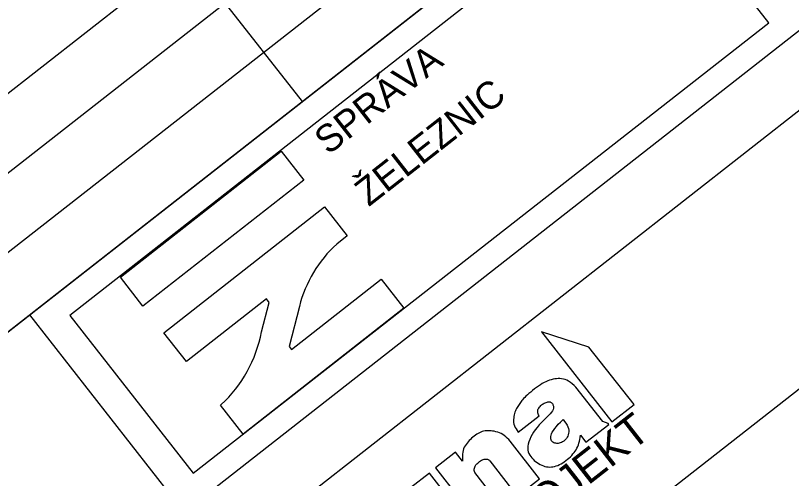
# Model space of a CAD drawing. Extents: x -651125 to -650955, y -1098339 to -1098183.
# Drawn here: x -650997.42 to -650981.93, y -1098225.14 to -1098215.9 of the extents above; entities that cross this region are included whole.
import ezdxf

# ---------------------------------------------------------------- set-up
doc = ezdxf.new("R2010")
doc.units = 0
for name, color, linetype in [('0_rozpiska', 7, 'Continuous'), ('0_rozpiska-netisk', 7, 'Continuous'), ('Default', 7, 'Continuous'), ('Rozpiska', 7, 'Continuous'), ('Rozpiska_Logo', 7, 'Continuous'), ('Rozpiska_pole_4', 7, 'Continuous'), ('Rozpiska_pole_6', 7, 'Continuous')]:
    doc.layers.add(name, color=color, linetype=linetype)

# ---------------------------------------------------------------- blocks, each defined once
blk = doc.blocks.new('_U4')
at = {"layer": 'Rozpiska_Logo'}
blk.add_lwpolyline([(-0.0008399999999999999, 0.0008199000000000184), (0.0008399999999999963, 0.0008199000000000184), (0.0008399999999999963, 0.0005175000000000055), (-0.0008399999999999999, 0.0005175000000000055)], close=True, dxfattribs=at)
for points in [[(-2.995834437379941e-06, -6.329999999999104e-05), (-0.0008399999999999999, -6.329999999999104e-05), (-0.0008399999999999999, 0.00023910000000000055), (0.0008399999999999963, 0.00023910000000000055), (0.0008399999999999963, -6.329999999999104e-05), (0.0007294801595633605, -6.330000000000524e-05)], [(-0.00020291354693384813, -0.0002497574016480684), (-2.995834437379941e-06, -9.900986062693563e-05), (-2.995834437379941e-06, -6.329999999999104e-05)], [(0.0001714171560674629, -0.0002774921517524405), (-9.743909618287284e-05, -0.00048589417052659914), (-9.743909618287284e-05, -0.0005174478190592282), (0.0008399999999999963, -0.0005174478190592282), (0.0008399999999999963, -0.000819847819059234), (-0.0008399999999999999, -0.000819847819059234), (-0.0008399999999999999, -0.0005174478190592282), (-0.0008331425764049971, -0.0005174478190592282)]]:
    blk.add_lwpolyline(points, dxfattribs=at)
for centre, radius, start, end in [((0.0008055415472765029, -0.0010955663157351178), 0.0010350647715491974, 94.21415970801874, 127.7807996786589), ((-0.0009201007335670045, 0.0005630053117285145), 0.0010839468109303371, 274.60142059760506, 311.4253943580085)]:
    blk.add_arc(centre, radius, start, end, dxfattribs=at)
blk = doc.blocks.new('_U3')
at = {"layer": 'Rozpiska_Logo'}
blk.add_blockref('_U4', (-0.0011065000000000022, -3.555000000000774e-05), dxfattribs=at)
at = {"layer": 'Rozpiska_pole_6'}
for s, p in [('SPRÁVA', (1.6969479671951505e-05, 0.0005179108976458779)), ('ŽELEZNIC', (1.6969479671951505e-05, -2.2089102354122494e-05))]:
    blk.add_text(s, height=0.00022500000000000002, dxfattribs=at).set_placement(p)
blk = doc.blocks.new('A$C346D018F')
at = {"layer": 'Rozpiska'}
for points in [[(-0.00741159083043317, 0.007120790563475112), (-0.00741159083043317, 0.012960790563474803), (-0.009651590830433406, 0.01624079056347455), (-0.009651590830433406, 0.007120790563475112)], [(-0.036140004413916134, 0.0068858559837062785), (-0.03577818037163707, 0.006902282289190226), (-0.03541167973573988, 0.006950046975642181), (-0.035040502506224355, 0.0070291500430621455), (-0.03466464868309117, 0.0071395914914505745), (-0.03430989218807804, 0.007275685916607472), (-0.034002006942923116, 0.007431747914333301), (-0.03374099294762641, 0.007607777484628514), (-0.033526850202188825, 0.0078037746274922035), (-0.033359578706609, 0.008019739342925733), (-0.03323917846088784, 0.00825567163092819), (-0.0331656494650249, 0.008511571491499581), (-0.03313899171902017, 0.008787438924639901), (-0.03314962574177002, 0.009060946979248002), (-0.03318797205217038, 0.009309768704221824), (-0.03325403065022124, 0.009533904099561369), (-0.03334780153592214, 0.009733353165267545), (-0.03346928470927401, 0.009908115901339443), (-0.03361848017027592, 0.010058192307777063), (-0.033795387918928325, 0.01018358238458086), (-0.03400000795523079, 0.010284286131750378), (-0.03421963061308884, 0.010370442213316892), (-0.03444154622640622, 0.01045218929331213), (-0.03466575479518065, 0.010529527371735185), (-0.03489225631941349, 0.01060245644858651), (-0.035121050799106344, 0.010670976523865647), (-0.03535213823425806, 0.010735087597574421), (-0.03558551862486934, 0.010794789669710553), (-0.035821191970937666, 0.010850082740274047), (-0.03604279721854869, 0.01090517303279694), (-0.036233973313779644, 0.010964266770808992), (-0.03639472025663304, 0.011027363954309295), (-0.03652503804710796, 0.011094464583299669), (-0.03662492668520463, 0.01116556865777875), (-0.036694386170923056, 0.011240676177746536), (-0.036733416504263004, 0.01131978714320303), (-0.03674201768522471, 0.01140290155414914), (-0.03672548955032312, 0.011482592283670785), (-0.036689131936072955, 0.011551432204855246), (-0.036632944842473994, 0.011609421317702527), (-0.03655692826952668, 0.011656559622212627), (-0.036461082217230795, 0.011692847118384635), (-0.03634540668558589, 0.01171828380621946), (-0.036209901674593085, 0.01173286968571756), (-0.036054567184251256, 0.011736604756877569), (-0.03589937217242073, 0.01172578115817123), (-0.03576428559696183, 0.011696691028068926), (-0.035649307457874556, 0.011649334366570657), (-0.03555443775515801, 0.011583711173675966), (-0.03547967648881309, 0.011499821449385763), (-0.035425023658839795, 0.011397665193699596), (-0.035390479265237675, 0.011277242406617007), (-0.035376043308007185, 0.011138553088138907), (-0.033297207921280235, 0.011138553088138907), (-0.03331636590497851, 0.011380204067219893), (-0.03337848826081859, 0.01160998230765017), (-0.03348350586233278, 0.011827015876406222), (-0.03363141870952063, 0.012031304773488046), (-0.03382222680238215, 0.012222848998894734), (-0.03405593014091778, 0.012401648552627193), (-0.03433252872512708, 0.012567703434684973), (-0.034652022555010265, 0.012721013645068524), (-0.034994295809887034, 0.012850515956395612), (-0.03533923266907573, 0.012945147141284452), (-0.03568683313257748, 0.013004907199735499), (-0.036037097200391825, 0.013029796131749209), (-0.03639002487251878, 0.013019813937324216), (-0.036745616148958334, 0.012974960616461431), (-0.037103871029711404, 0.012895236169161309), (-0.03746478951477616, 0.012780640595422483), (-0.037802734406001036, 0.012638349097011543), (-0.03809206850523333, 0.012475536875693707), (-0.03833279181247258, 0.012292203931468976), (-0.038524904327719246, 0.012088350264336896), (-0.03866840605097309, 0.011863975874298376), (-0.03876329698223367, 0.011619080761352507), (-0.03880957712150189, 0.011353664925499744), (-0.03880724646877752, 0.011067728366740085), (-0.03876748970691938, 0.010786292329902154), (-0.038701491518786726, 0.010534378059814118), (-0.03860925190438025, 0.01031198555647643), (-0.03849077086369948, 0.010119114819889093), (-0.038346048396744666, 0.009955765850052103), (-0.03817508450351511, 0.00982193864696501), (-0.0379778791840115, 0.009717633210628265), (-0.037754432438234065, 0.009642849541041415), (-0.03751966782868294, 0.00958297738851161), (-0.03728850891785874, 0.009523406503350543), (-0.037060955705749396, 0.00946413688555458), (-0.036837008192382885, 0.009405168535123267), (-0.036616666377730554, 0.0093465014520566), (-0.036399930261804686, 0.009288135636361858), (-0.03618679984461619, 0.0092300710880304), (-0.03597727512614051, 0.009172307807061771), (-0.035784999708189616, 0.009112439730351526), (-0.03562361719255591, 0.00904806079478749), (-0.03549312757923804, 0.008979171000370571), (-0.03539353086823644, 0.008905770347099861), (-0.035324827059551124, 0.008827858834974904), (-0.035287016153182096, 0.008745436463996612), (-0.035280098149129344, 0.008658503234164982), (-0.03530407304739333, 0.00856705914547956), (-0.03535068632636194, 0.008479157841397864), (-0.03541168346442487, 0.008402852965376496), (-0.03548706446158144, 0.008338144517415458), (-0.035576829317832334, 0.00828503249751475), (-0.03568097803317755, 0.00824351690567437), (-0.035799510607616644, 0.008213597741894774), (-0.035932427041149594, 0.008195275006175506), (-0.03607972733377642, 0.00818854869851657), (-0.03622803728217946, 0.008198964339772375), (-0.03636398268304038, 0.008232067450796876), (-0.03648756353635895, 0.008287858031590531), (-0.03659877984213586, 0.00836633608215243), (-0.03669763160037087, 0.008467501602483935), (-0.03678411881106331, 0.008591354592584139), (-0.036858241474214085, 0.008737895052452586), (-0.03691961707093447, 0.008906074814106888), (-0.03899999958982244, 0.008906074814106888), (-0.03895611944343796, 0.008599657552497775), (-0.038872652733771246, 0.008317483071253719), (-0.038749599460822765, 0.008059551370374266), (-0.038586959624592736, 0.00782586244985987), (-0.03838473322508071, 0.007616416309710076), (-0.03814292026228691, 0.007431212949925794), (-0.03786152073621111, 0.00727025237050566), (-0.03754053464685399, 0.007133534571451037), (-0.037197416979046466, 0.007024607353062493), (-0.036849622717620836, 0.0069470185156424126), (-0.036497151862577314, 0.006900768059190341)], [(-0.026592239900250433, 0.00507853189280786), (-0.02642366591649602, 0.005082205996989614), (-0.026253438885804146, 0.005090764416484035), (-0.026081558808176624, 0.005104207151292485), (-0.025908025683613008, 0.00512253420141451), (-0.02573380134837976, 0.005149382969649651), (-0.025559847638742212, 0.005188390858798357), (-0.025386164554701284, 0.00523955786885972), (-0.02521275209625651, 0.005302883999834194), (-0.025039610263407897, 0.005378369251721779), (-0.024866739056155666, 0.0054660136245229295), (-0.02469413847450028, 0.0055658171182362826), (-0.024521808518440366, 0.005677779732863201), (-0.024357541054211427, 0.0058073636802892), (-0.024209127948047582, 0.005960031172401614), (-0.024076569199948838, 0.006135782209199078), (-0.023959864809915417, 0.006334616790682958), (-0.023859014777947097, 0.0065565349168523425), (-0.023774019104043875, 0.006801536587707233), (-0.023704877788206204, 0.007069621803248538), (-0.023651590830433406, 0.007360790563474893), (-0.023651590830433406, 0.012880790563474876), (-0.025571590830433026, 0.012880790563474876), (-0.025571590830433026, 0.01216079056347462), (-0.025837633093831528, 0.012415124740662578), (-0.026107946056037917, 0.012628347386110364), (-0.026382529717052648, 0.012800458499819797), (-0.026661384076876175, 0.01293145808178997), (-0.02694450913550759, 0.013021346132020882), (-0.027231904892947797, 0.013070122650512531), (-0.027523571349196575, 0.013077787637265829), (-0.027819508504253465, 0.01304434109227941), (-0.028106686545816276, 0.012976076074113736), (-0.02837207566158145, 0.012879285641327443), (-0.02861567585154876, 0.012753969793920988), (-0.028837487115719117, 0.012600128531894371), (-0.029037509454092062, 0.012417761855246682), (-0.029215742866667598, 0.01220686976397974), (-0.02937218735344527, 0.011967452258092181), (-0.029506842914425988, 0.011699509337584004), (-0.02961763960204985, 0.011413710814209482), (-0.029702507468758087, 0.011120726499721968), (-0.0297614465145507, 0.010820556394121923), (-0.02979445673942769, 0.010513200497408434), (-0.0298015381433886, 0.010198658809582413), (-0.02978269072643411, 0.009876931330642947), (-0.029737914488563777, 0.009548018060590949), (-0.02966720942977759, 0.009211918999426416), (-0.02956719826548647, 0.008888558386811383), (-0.029434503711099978, 0.008597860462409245), (-0.029269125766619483, 0.008339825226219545), (-0.029071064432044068, 0.008114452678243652), (-0.02884031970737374, 0.007921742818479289), (-0.02857689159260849, 0.007761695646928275), (-0.028280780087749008, 0.0076343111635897), (-0.027951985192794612, 0.007539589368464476), (-0.027615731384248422, 0.007481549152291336), (-0.02729724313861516, 0.007464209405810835), (-0.026996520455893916, 0.007487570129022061), (-0.02671356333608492, 0.007551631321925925), (-0.026448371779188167, 0.007656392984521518), (-0.026200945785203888, 0.0078018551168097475), (-0.025971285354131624, 0.007988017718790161), (-0.025759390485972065, 0.008214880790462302), (-0.025759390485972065, 0.00713805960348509), (-0.02577803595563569, 0.007050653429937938), (-0.02580115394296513, 0.006968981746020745), (-0.025828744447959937, 0.0068930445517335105), (-0.025860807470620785, 0.0068228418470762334), (-0.025897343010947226, 0.006758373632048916), (-0.025938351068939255, 0.006699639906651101), (-0.02598383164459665, 0.006646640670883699), (-0.026033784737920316, 0.0065993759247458), (-0.026089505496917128, 0.006557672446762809), (-0.02615228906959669, 0.006521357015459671), (-0.026222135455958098, 0.0064904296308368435), (-0.0262990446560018, 0.006464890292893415), (-0.026383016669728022, 0.006444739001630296), (-0.026474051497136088, 0.006429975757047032), (-0.02657214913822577, 0.006420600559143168), (-0.026677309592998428, 0.006416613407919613), (-0.026780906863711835, 0.006421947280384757), (-0.026874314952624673, 0.006440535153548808), (-0.02695753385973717, 0.006472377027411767), (-0.027030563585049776, 0.006517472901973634), (-0.0270934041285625, 0.006575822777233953), (-0.02714605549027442, 0.00664742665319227), (-0.027188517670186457, 0.006732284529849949), (-0.02722079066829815, 0.006830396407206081), (-0.02952826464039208, 0.006830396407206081), (-0.029458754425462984, 0.006602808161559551), (-0.02937545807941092, 0.006393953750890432), (-0.029278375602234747, 0.0062038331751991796), (-0.029167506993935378, 0.0060324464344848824), (-0.029042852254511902, 0.005879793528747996), (-0.028904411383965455, 0.0057458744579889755), (-0.0287521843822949, 0.005630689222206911), (-0.028586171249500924, 0.005534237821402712), (-0.028414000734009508, 0.005451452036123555), (-0.028243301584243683, 0.005377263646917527), (-0.028074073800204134, 0.0053116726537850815), (-0.027906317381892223, 0.005254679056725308), (-0.027740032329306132, 0.005206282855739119), (-0.02757521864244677, 0.005166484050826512), (-0.027411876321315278, 0.005135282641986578), (-0.027250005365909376, 0.0051126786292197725), (-0.027088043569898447, 0.005096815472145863), (-0.026924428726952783, 0.005085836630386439), (-0.026759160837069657, 0.00507974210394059)], [(-0.01701159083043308, 0.007120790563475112), (-0.01701159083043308, 0.01092079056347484), (-0.017014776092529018, 0.011090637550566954), (-0.017028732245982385, 0.011253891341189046), (-0.017053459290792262, 0.011410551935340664), (-0.01708895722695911, 0.01156061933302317), (-0.01713522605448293, 0.011704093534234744), (-0.01719226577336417, 0.011840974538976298), (-0.017260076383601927, 0.011971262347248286), (-0.01733865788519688, 0.012094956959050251), (-0.017423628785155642, 0.012211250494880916), (-0.01751060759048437, 0.01231933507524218), (-0.01759959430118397, 0.012419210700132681), (-0.01769058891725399, 0.012510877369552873), (-0.017783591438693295, 0.012594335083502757), (-0.017878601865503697, 0.012669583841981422), (-0.017975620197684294, 0.012736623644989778), (-0.018074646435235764, 0.012795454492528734), (-0.018176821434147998, 0.012846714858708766), (-0.018283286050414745, 0.012891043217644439), (-0.018394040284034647, 0.012928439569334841), (-0.018509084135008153, 0.012958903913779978), (-0.018628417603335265, 0.012982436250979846), (-0.018752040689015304, 0.012999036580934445), (-0.0188799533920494, 0.01300870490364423), (-0.01901215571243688, 0.013011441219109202), (-0.019145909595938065, 0.01300824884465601), (-0.019278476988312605, 0.013000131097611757), (-0.019409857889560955, 0.012987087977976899), (-0.0195400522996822, 0.012969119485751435), (-0.019669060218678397, 0.012946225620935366), (-0.01979688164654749, 0.012918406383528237), (-0.019923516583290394, 0.012885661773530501), (-0.02004896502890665, 0.01284799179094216), (-0.020172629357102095, 0.012799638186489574), (-0.020293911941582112, 0.012734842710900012), (-0.02041281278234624, 0.012653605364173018), (-0.020529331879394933, 0.01255592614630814), (-0.020643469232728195, 0.012441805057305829), (-0.020755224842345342, 0.012311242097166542), (-0.020864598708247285, 0.012164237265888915), (-0.020971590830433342, 0.012000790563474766), (-0.020971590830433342, 0.01292079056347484), (-0.02301159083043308, 0.01292079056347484), (-0.02301159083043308, 0.007120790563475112), (-0.020771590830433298, 0.007120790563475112), (-0.020771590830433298, 0.010680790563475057), (-0.02073712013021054, 0.010771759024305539), (-0.020692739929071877, 0.010852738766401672), (-0.02063845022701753, 0.010923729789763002), (-0.020574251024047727, 0.010984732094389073), (-0.020500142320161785, 0.011035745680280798), (-0.020416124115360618, 0.011076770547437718), (-0.02032219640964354, 0.011107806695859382), (-0.02021835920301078, 0.011128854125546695), (-0.020112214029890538, 0.011141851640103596), (-0.0200113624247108, 0.011148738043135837), (-0.019915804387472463, 0.011149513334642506), (-0.019825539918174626, 0.011144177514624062), (-0.01974056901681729, 0.011132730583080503), (-0.01966089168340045, 0.011115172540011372), (-0.01958650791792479, 0.011091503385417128), (-0.019517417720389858, 0.011061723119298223), (-0.019455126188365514, 0.011027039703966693), (-0.019401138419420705, 0.010988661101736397), (-0.019355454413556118, 0.01094658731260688), (-0.019318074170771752, 0.010900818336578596), (-0.019288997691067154, 0.010851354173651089), (-0.01926822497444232, 0.010798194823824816), (-0.019255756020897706, 0.01074134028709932), (-0.019251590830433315, 0.010680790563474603), (-0.019251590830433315, 0.007120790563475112)], [(-0.030451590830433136, 0.007120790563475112), (-0.030451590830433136, 0.012800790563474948), (-0.032451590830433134, 0.012800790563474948), (-0.032451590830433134, 0.007120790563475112)], [(-0.014448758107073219, 0.00695666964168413), (-0.014286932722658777, 0.006959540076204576), (-0.014129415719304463, 0.006968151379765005), (-0.01397620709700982, 0.00698250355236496), (-0.01382730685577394, 0.007002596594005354), (-0.0136827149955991, 0.00702843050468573), (-0.013542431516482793, 0.007060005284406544), (-0.013406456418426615, 0.007097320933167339), (-0.013274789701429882, 0.007140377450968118), (-0.01314610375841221, 0.007191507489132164), (-0.013019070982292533, 0.007253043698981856), (-0.01289369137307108, 0.007324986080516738), (-0.012769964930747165, 0.007407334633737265), (-0.012647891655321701, 0.007500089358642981), (-0.012527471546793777, 0.007603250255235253), (-0.012408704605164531, 0.0077168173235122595), (-0.01229159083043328, 0.007840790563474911), (-0.01229159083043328, 0.007120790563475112), (-0.009971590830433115, 0.007120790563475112), (-0.009971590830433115, 0.007200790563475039), (-0.010211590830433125, 0.00760079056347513), (-0.010211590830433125, 0.011080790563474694), (-0.010237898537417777, 0.011285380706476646), (-0.010273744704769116, 0.011475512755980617), (-0.010319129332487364, 0.011651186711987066), (-0.01037405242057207, 0.011812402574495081), (-0.01043851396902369, 0.011959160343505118), (-0.010512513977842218, 0.012091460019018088), (-0.010596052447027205, 0.012209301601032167), (-0.010689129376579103, 0.012312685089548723), (-0.010790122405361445, 0.012405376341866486), (-0.010897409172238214, 0.012491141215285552), (-0.011010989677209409, 0.012569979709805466), (-0.011130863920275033, 0.012641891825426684), (-0.01125703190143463, 0.012706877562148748), (-0.01138949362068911, 0.01276493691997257), (-0.011528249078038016, 0.012816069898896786), (-0.011673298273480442, 0.012860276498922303), (-0.011825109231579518, 0.01289816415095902), (-0.011984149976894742, 0.012930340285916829), (-0.012150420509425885, 0.012956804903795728), (-0.01232392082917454, 0.012977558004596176), (-0.012504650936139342, 0.012992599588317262), (-0.012692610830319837, 0.013001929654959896), (-0.012887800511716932, 0.01300554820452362), (-0.013090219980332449, 0.013003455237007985), (-0.013288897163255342, 0.012997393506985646), (-0.013472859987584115, 0.012989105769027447), (-0.013642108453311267, 0.012978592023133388), (-0.013796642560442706, 0.012965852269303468), (-0.013936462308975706, 0.012950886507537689), (-0.014061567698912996, 0.01293369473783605), (-0.014171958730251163, 0.01291427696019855), (-0.014267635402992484, 0.01289263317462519), (-0.014356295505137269, 0.012868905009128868), (-0.014445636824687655, 0.012843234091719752), (-0.014535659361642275, 0.012815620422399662), (-0.01462636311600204, 0.012786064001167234), (-0.014717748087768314, 0.012754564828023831), (-0.014809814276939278, 0.012721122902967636), (-0.014902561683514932, 0.012685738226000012), (-0.014995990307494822, 0.012648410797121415), (-0.015089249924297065, 0.012606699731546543), (-0.015181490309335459, 0.012558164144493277), (-0.015272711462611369, 0.012502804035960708), (-0.01536291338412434, 0.012440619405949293), (-0.015452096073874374, 0.012371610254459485), (-0.01554025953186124, 0.012295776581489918), (-0.015627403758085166, 0.012213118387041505), (-0.015713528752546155, 0.012123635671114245), (-0.015793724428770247, 0.012026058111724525), (-0.015863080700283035, 0.011919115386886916), (-0.015921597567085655, 0.011802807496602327), (-0.015969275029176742, 0.01167713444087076), (-0.016006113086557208, 0.011542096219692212), (-0.01603211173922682, 0.01139769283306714), (-0.016047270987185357, 0.011243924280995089), (-0.016051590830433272, 0.011080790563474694), (-0.013931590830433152, 0.011080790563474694), (-0.013916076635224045, 0.011177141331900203), (-0.013891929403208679, 0.011264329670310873), (-0.013859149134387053, 0.01134235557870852), (-0.013817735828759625, 0.011411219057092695), (-0.013767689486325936, 0.011470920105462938), (-0.013709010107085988, 0.011521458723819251), (-0.013641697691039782, 0.01156283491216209), (-0.01356575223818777, 0.011595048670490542), (-0.01348522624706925, 0.011619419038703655), (-0.013404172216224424, 0.011637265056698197), (-0.01332259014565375, 0.011648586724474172), (-0.013240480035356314, 0.011653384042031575), (-0.013157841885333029, 0.011651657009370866), (-0.013074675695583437, 0.01164340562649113), (-0.012990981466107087, 0.011628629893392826), (-0.012906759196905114, 0.011607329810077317), (-0.01282664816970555, 0.011581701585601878), (-0.012755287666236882, 0.011553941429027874), (-0.012692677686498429, 0.011524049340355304), (-0.012638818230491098, 0.011492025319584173), (-0.01259370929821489, 0.011457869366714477), (-0.012557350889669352, 0.011421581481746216), (-0.01252974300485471, 0.011383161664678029), (-0.012510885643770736, 0.011342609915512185), (-0.012499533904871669, 0.011299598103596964), (-0.012494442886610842, 0.01125379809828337), (-0.012495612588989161, 0.011205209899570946), (-0.01250304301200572, 0.01115383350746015), (-0.01251673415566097, 0.011099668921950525), (-0.01253668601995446, 0.011042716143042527), (-0.012562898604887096, 0.010982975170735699), (-0.012595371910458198, 0.010920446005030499), (-0.012646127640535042, 0.010859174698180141), (-0.012727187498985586, 0.01080320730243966), (-0.012838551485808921, 0.010752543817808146), (-0.012980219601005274, 0.01070718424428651), (-0.01315219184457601, 0.010667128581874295), (-0.013354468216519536, 0.010632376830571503), (-0.013587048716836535, 0.010602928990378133), (-0.013849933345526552, 0.01057878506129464), (-0.014121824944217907, 0.010552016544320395), (-0.014381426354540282, 0.010514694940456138), (-0.014628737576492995, 0.010466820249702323), (-0.01486375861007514, 0.010408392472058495), (-0.015086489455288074, 0.010339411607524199), (-0.01529693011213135, 0.010259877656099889), (-0.015495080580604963, 0.010169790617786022), (-0.015680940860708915, 0.010069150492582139), (-0.015850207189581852, 0.00996098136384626), (-0.01599857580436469, 0.009848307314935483), (-0.01612604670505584, 0.009731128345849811), (-0.016232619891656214, 0.0096094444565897), (-0.016318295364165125, 0.009483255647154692), (-0.016383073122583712, 0.009352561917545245), (-0.016426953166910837, 0.009217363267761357), (-0.016449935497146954, 0.00907765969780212), (-0.016457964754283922, 0.008936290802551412), (-0.016456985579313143, 0.008796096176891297), (-0.016446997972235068, 0.008657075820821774), (-0.016428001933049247, 0.008519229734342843), (-0.01639999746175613, 0.008382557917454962), (-0.016362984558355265, 0.008247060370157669), (-0.016316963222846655, 0.008112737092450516), (-0.016261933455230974, 0.007979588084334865), (-0.016198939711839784, 0.007851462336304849), (-0.016129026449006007, 0.007732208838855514), (-0.016052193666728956, 0.007621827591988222), (-0.015968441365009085, 0.007520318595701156), (-0.0158777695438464, 0.0074276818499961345), (-0.015780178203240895, 0.007343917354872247), (-0.015675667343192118, 0.007269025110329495), (-0.015564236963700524, 0.0072030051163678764), (-0.015446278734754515, 0.007145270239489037), (-0.015322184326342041, 0.007095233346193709), (-0.015191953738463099, 0.007052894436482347), (-0.015055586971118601, 0.007018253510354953), (-0.014913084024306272, 0.006991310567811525), (-0.014764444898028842, 0.006972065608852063), (-0.014609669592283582, 0.006960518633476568)], [(-0.013733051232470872, 0.008301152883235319), (-0.013835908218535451, 0.008321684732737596), (-0.013930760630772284, 0.008349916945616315), (-0.01401760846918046, 0.008385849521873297), (-0.014096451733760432, 0.008429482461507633), (-0.014167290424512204, 0.008480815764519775), (-0.014230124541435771, 0.008539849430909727), (-0.014284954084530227, 0.00860658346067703), (-0.014331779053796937, 0.00868101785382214), (-0.014366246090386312, 0.008758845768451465), (-0.014384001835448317, 0.008835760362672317), (-0.014385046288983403, 0.008911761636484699), (-0.014369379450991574, 0.008986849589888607), (-0.014337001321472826, 0.009061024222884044), (-0.014287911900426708, 0.009134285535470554), (-0.014222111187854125, 0.009206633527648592), (-0.014139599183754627, 0.009278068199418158), (-0.01403613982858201, 0.00934639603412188), (-0.013907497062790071, 0.009409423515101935), (-0.013753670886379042, 0.00946715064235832), (-0.013574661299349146, 0.009519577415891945), (-0.013370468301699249, 0.009566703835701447), (-0.013141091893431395, 0.009608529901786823), (-0.012886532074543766, 0.009645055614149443), (-0.012606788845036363, 0.00967628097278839), (-0.012602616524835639, 0.009478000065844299), (-0.012611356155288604, 0.009295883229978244), (-0.012633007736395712, 0.009129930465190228), (-0.012667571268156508, 0.008980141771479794), (-0.012715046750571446, 0.008846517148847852), (-0.012775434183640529, 0.008729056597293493), (-0.012848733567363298, 0.008627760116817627), (-0.012934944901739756, 0.008542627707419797), (-0.013028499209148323, 0.008471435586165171), (-0.013123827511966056, 0.008411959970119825), (-0.013220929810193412, 0.008364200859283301), (-0.013319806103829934, 0.008328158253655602), (-0.013420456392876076, 0.008303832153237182), (-0.013522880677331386, 0.008291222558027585), (-0.013627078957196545, 0.008290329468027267)]]:
    blk.add_lwpolyline(points, close=True, dxfattribs=at)
blk.add_circle((-0.031451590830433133, 0.015280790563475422), 0.0013200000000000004, dxfattribs=at)
blk.add_ellipse((-0.026691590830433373, 0.01028079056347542), major_axis=(7.102951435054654e-20, 0.0011600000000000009), ratio=0.7586206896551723, dxfattribs=at)
blk.add_text('PROJEKT', height=0.0025000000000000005, dxfattribs=at).set_placement((-0.023210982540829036, 0.004277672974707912))

msp = doc.modelspace()

# ---------------------------------------------------------------- linework, layer by layer
at = {"layer": '0_rozpiska'}
for p, q in [((-651018.1347919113, -1098238.309072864), (-650984.6628319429, -1098212.119802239)), ((-651018.3449765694, -1098238.4735264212), (-650984.8730166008, -1098212.2842557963)), ((-650981.5817412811, -1098216.0576798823), (-651015.0537012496, -1098242.2469505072)), ((-651014.2834285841, -1098243.2314199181), (-650980.8114686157, -1098217.0421492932)), ((-651011.5874742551, -1098246.677062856), (-650978.1155142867, -1098220.4877922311))]:
    msp.add_line(p, q, dxfattribs=at)
at = {"layer": '0_rozpiska-netisk'}
msp.add_line((-650997.1360593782, -1098221.87915691), (-650987.892787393, -1098233.6927898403), dxfattribs=at)
msp.add_lwpolyline([(-650984.846957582, -1098212.898726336), (-650984.846957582, -1098212.898726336), (-650996.3357156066, -1098221.8878083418), (-650993.8708430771, -1098225.0381104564), (-650982.3820850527, -1098216.0490284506)], close=True, dxfattribs=at)
at = {"layer": 'Rozpiska_pole_4'}
for p, q in [((-651020.4456099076, -1098235.3556646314), (-650986.9736499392, -1098209.1663940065)), ((-651019.6753372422, -1098236.3401340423), (-650986.2033772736, -1098210.1508634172)), ((-651018.9050645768, -1098237.324603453), (-650985.4331046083, -1098211.1353328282)), ((-650991.6919435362, -1098217.6195490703), (-650995.5433068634, -1098212.697202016))]:
    msp.add_line(p, q, dxfattribs=at)
msp.add_lwpolyline([(-651021.9861552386, -1098233.38672581), (-650988.5141952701, -1098207.1974551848), (-650984.6628319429, -1098212.119802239), (-651018.1347919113, -1098238.309072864)], close=True, dxfattribs=at)

# ---------------------------------------------------------------- block references
at = {"layer": '0_rozpiska', "xscale": 2425.7475, "yscale": 2425.7475, "rotation": 38.04048537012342}
msp.add_blockref('_U3', (-650990.4333115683, -1098219.7138612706), dxfattribs=at)
at = {"layer": 'Default', "xscale": 250, "yscale": 250, "rotation": 38.04048537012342}
msp.add_blockref('A$C346D018F', (-650982.5154130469, -1098223.9303793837), dxfattribs=at)

doc.saveas('drawing.dxf')
